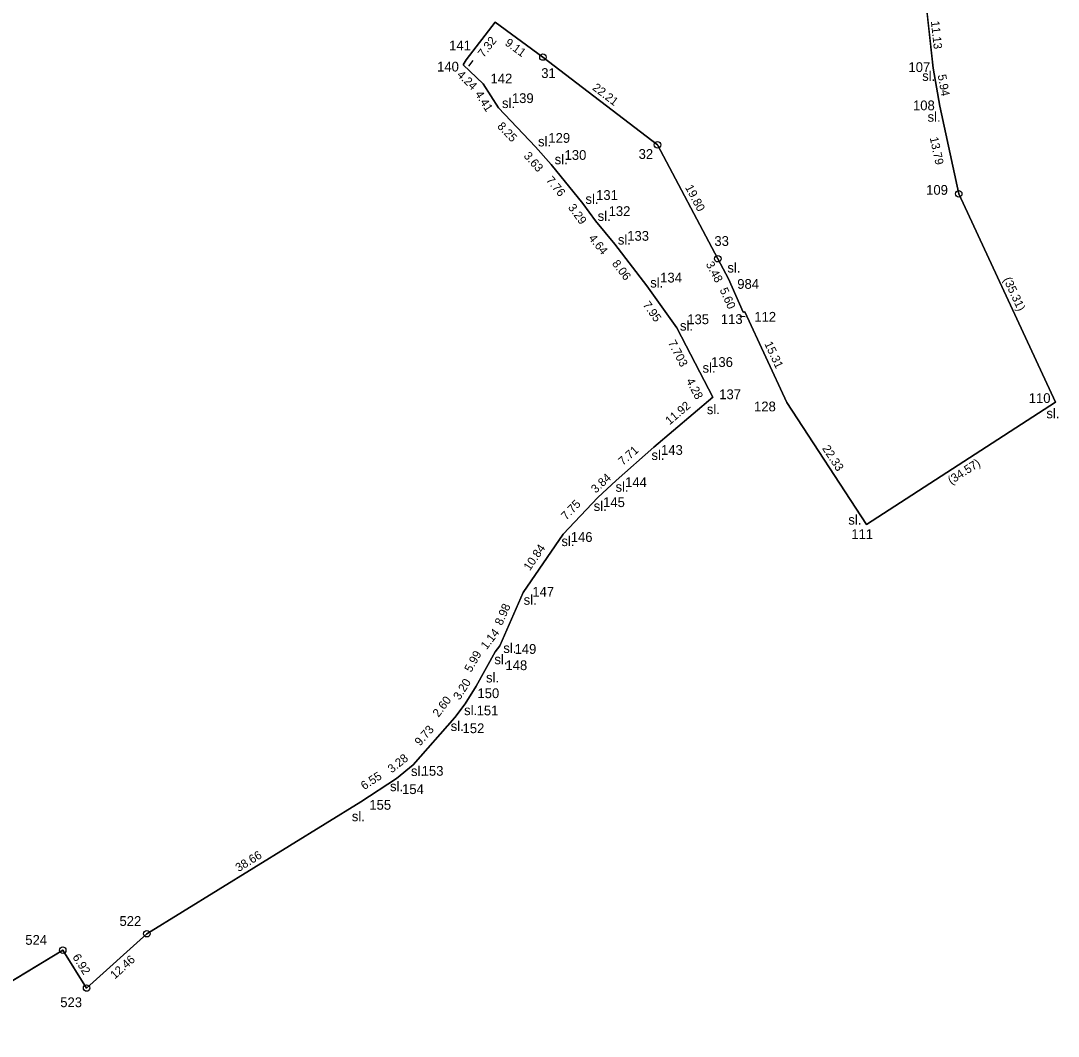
# Model space of a CAD drawing. Extents: x -555170 to -550532, y -1039598 to -1034701.
# Drawn here: x -553508.8 to -553349.4, y -1037298.8 to -1037142.8 of the extents above; entities that cross this region are included whole.
import ezdxf

# ---------------------------------------------------------------- set-up
doc = ezdxf.new("R2010")
doc.units = 0
for name, color, linetype in [('Vrstva 10', 7, 'Continuous'), ('Vrstva 40', 7, 'Continuous'), ('Vrstva 43', 7, 'Continuous'), ('Vrstva 48', 7, 'Continuous')]:
    doc.layers.add(name, color=color, linetype=linetype)

msp = doc.modelspace()

# ---------------------------------------------------------------- linework, layer by layer
at = {"layer": 'Vrstva 10'}
for p, q in [((-553439.38, -1037148.94), (-553440.05, -1037149.8)), ((-553397.55, -1037188.3), (-553398.36, -1037188.25))]:
    msp.add_line(p, q, dxfattribs=at)
at = {"layer": 'Vrstva 40'}
for p, q in [((-553368.67, -1037150.1), (-553369.86, -1037139.04)), ((-553440.38, -1037148.86), (-553435.92, -1037143.06)), ((-553435.92, -1037143.06), (-553428.6, -1037148.42)), ((-553440.84, -1037149.59), (-553440.38, -1037148.86)), ((-553437.77, -1037152.52), (-553440.84, -1037149.59)), ((-553428.6, -1037148.42), (-553410.99, -1037161.89)), ((-553367.62, -1037155.95), (-553368.67, -1037150.1)), ((-553435.44, -1037156.23), (-553437.77, -1037152.52)), ((-553429.76, -1037162.19), (-553435.44, -1037156.23)), ((-553364.73, -1037169.41), (-553367.62, -1037155.95)), ((-553427.36, -1037164.9), (-553429.76, -1037162.19)), ((-553410.99, -1037161.89), (-553401.73, -1037179.39)), ((-553422.45, -1037170.91), (-553427.36, -1037164.9)), ((-553349.86, -1037201.44), (-553364.73, -1037169.41)), ((-553420.52, -1037173.56), (-553422.45, -1037170.91)), ((-553417.58, -1037177.15), (-553420.52, -1037173.56)), ((-553412.65, -1037183.53), (-553417.58, -1037177.15)), ((-553401.73, -1037179.39), (-553400.1, -1037182.46)), ((-553400.1, -1037182.46), (-553397.85, -1037187.58)), ((-553408.03, -1037190.02), (-553412.65, -1037183.53)), ((-553397.85, -1037187.58), (-553397.59, -1037187.57)), ((-553397.59, -1037187.57), (-553391.13, -1037201.49)), ((-553404.48, -1037196.83), (-553408.03, -1037190.02)), ((-553402.51, -1037200.63), (-553404.48, -1037196.83)), ((-553411.55, -1037208.33), (-553402.51, -1037200.63)), ((-553391.13, -1037201.49), (-553378.91, -1037220.18)), ((-553378.91, -1037220.18), (-553349.86, -1037201.44)), ((-553417.35, -1037213.46), (-553411.55, -1037208.33)), ((-553420.17, -1037216.07), (-553417.35, -1037213.46)), ((-553425.49, -1037221.7), (-553420.17, -1037216.07)), ((-553431.62, -1037230.63), (-553425.49, -1037221.7)), ((-553435.21, -1037238.86), (-553431.62, -1037230.63)), ((-553435.92, -1037239.78), (-553435.21, -1037238.86)), ((-553438.85, -1037245.01), (-553435.92, -1037239.78)), ((-553440.56, -1037247.73), (-553438.85, -1037245.01)), ((-553442.13, -1037249.82), (-553440.56, -1037247.73)), ((-553448.52, -1037257.14), (-553442.13, -1037249.82)), ((-553451.08, -1037259.19), (-553448.52, -1037257.14)), ((-553456.55, -1037262.79), (-553451.08, -1037259.19)), ((-553489.45, -1037283.05), (-553456.55, -1037262.79)), ((-553498.7, -1037291.39), (-553489.45, -1037283.05)), ((-553524.22, -1037298.8), (-553502.37, -1037285.57)), ((-553502.37, -1037285.57), (-553498.7, -1037291.39))]:
    msp.add_line(p, q, dxfattribs=at)
at = {"layer": 'Vrstva 43'}
for p, q in [((-553435.92, -1037143.06), (-553435.92, -1037143.06)), ((-553440.84, -1037149.59), (-553440.84, -1037149.59)), ((-553440.38, -1037148.86), (-553440.38, -1037148.86)), ((-553428.6, -1037148.42), (-553428.6, -1037148.42)), ((-553368.67, -1037150.1), (-553368.67, -1037150.1)), ((-553437.77, -1037152.52), (-553437.77, -1037152.52)), ((-553435.44, -1037156.23), (-553435.44, -1037156.23)), ((-553367.62, -1037155.95), (-553367.62, -1037155.95)), ((-553429.76, -1037162.19), (-553429.76, -1037162.19)), ((-553410.99, -1037161.89), (-553410.99, -1037161.89)), ((-553427.36, -1037164.9), (-553427.36, -1037164.9)), ((-553364.73, -1037169.41), (-553364.73, -1037169.41)), ((-553422.45, -1037170.91), (-553422.45, -1037170.91)), ((-553420.52, -1037173.56), (-553420.52, -1037173.56)), ((-553417.58, -1037177.15), (-553417.58, -1037177.15)), ((-553401.73, -1037179.39), (-553401.73, -1037179.39)), ((-553400.1, -1037182.46), (-553400.1, -1037182.46)), ((-553412.65, -1037183.53), (-553412.65, -1037183.53)), ((-553397.85, -1037187.58), (-553397.85, -1037187.58)), ((-553397.59, -1037187.57), (-553397.59, -1037187.57)), ((-553408.03, -1037190.02), (-553408.03, -1037190.02)), ((-553404.48, -1037196.83), (-553404.48, -1037196.83)), ((-553402.51, -1037200.63), (-553402.51, -1037200.63)), ((-553391.13, -1037201.49), (-553391.13, -1037201.49)), ((-553349.86, -1037201.44), (-553349.86, -1037201.44)), ((-553411.55, -1037208.33), (-553411.55, -1037208.33)), ((-553417.35, -1037213.46), (-553417.35, -1037213.46)), ((-553420.17, -1037216.07), (-553420.17, -1037216.07)), ((-553378.91, -1037220.18), (-553378.91, -1037220.18)), ((-553425.49, -1037221.7), (-553425.49, -1037221.7)), ((-553431.62, -1037230.63), (-553431.62, -1037230.63)), ((-553435.21, -1037238.86), (-553435.21, -1037238.86)), ((-553435.92, -1037239.78), (-553435.92, -1037239.78)), ((-553438.85, -1037245.01), (-553438.85, -1037245.01)), ((-553440.56, -1037247.73), (-553440.56, -1037247.73)), ((-553442.13, -1037249.82), (-553442.13, -1037249.82)), ((-553448.52, -1037257.14), (-553448.52, -1037257.14)), ((-553451.08, -1037259.19), (-553451.08, -1037259.19)), ((-553456.55, -1037262.79), (-553456.55, -1037262.79)), ((-553489.45, -1037283.05), (-553489.45, -1037283.05)), ((-553502.37, -1037285.57), (-553502.37, -1037285.57)), ((-553498.7, -1037291.39), (-553498.7, -1037291.39))]:
    msp.add_line(p, q, dxfattribs=at)
for centre, radius in [((-553428.6, -1037148.42), 0.5), ((-553428.6, -1037148.42), 0.01), ((-553410.99, -1037161.89), 0.5), ((-553410.99, -1037161.89), 0.01), ((-553364.73, -1037169.41), 0.5), ((-553364.73, -1037169.41), 0.01), ((-553401.73, -1037179.39), 0.5), ((-553401.73, -1037179.39), 0.01), ((-553489.45, -1037283.05), 0.5), ((-553489.45, -1037283.05), 0.01), ((-553502.37, -1037285.57), 0.5), ((-553502.37, -1037285.57), 0.01), ((-553498.7, -1037291.39), 0.5), ((-553498.7, -1037291.39), 0.01)]:
    msp.add_circle(centre, radius, dxfattribs=at)
at = {"layer": 'Vrstva 48'}
msp.add_lwpolyline([(-553369.86, -1037139.04), (-553368.67, -1037150.1), (-553367.62, -1037155.95), (-553364.73, -1037169.41), (-553349.86, -1037201.44), (-553378.91, -1037220.18), (-553391.13, -1037201.49), (-553397.59, -1037187.57), (-553397.85, -1037187.58), (-553400.1, -1037182.46), (-553401.73, -1037179.39), (-553410.99, -1037161.89), (-553428.6, -1037148.42), (-553435.92, -1037143.06), (-553440.38, -1037148.86), (-553440.84, -1037149.59), (-553437.77, -1037152.52), (-553435.44, -1037156.23), (-553429.76, -1037162.19), (-553427.36, -1037164.9), (-553422.45, -1037170.91), (-553420.52, -1037173.56), (-553417.58, -1037177.15), (-553412.65, -1037183.53), (-553408.03, -1037190.02), (-553404.48, -1037196.83), (-553402.51, -1037200.63), (-553411.55, -1037208.33), (-553417.35, -1037213.46), (-553420.17, -1037216.07), (-553425.49, -1037221.7), (-553431.62, -1037230.63), (-553435.21, -1037238.86), (-553435.92, -1037239.78), (-553438.85, -1037245.01), (-553440.56, -1037247.73), (-553442.13, -1037249.82), (-553448.52, -1037257.14), (-553451.08, -1037259.19), (-553456.55, -1037262.79), (-553489.45, -1037283.05), (-553498.7, -1037291.39), (-553502.37, -1037285.57), (-553524.22, -1037298.8)], dxfattribs=at)

# ---------------------------------------------------------------- texts
at = {"layer": 'Vrstva 10'}
for s, rotation, p in [('11.13', 276.1411, (-553369, -1037142.93)), ('7.32', 52.441, (-553437.7, -1037148.58)), ('9.11', 323.7937, (-553434.55, -1037146.48)), ('4.24', 316.3367, (-553441.91, -1037151.27)), ('5.94', 280.1755, (-553367.96, -1037151.19)), ('22.21', 322.5709, (-553421.1, -1037153.34)), ('4.41', 302.1302, (-553439.09, -1037154.09)), ('8.25', 313.622, (-553435.71, -1037159.14)), ('13.79', 282.118, (-553369.18, -1037160.82)), ('3.63', 311.5284, (-553431.64, -1037163.66)), ('7.76', 309.2478, (-553428.18, -1037167.36)), ('19.80', 297.9091, (-553406.8, -1037168.43)), ('3.29', 306.0659, (-553424.81, -1037171.53)), ('4.64', 309.3155, (-553421.67, -1037176.28)), ('8.06', 307.6942, (-553418.06, -1037180.17)), ('3.48', 297.9091, (-553403.62, -1037180.22)), ('(35.31)', 294.9032, (-553357.91, -1037182.56)), ('5.60', 293.7232, (-553401.48, -1037184.16)), ('7.95', 305.4457, (-553413.32, -1037186.48)), ('7.703', 297.5327, (-553409.43, -1037192.28)), ('15.31', 294.8951, (-553394.61, -1037192.44)), ('4.28', 297.4032, (-553406.64, -1037198.13)), ('11.92', 40.4234, (-553409.13, -1037204.98)), ('7.71', 41.4922, (-553416.32, -1037211.21)), ('22.33', 303.1777, (-553385.76, -1037208.52)), ('(34.57)', 32.8258, (-553365.89, -1037214.1)), ('3.84', 42.7852, (-553420.49, -1037215.48)), ('7.75', 46.6216, (-553425.01, -1037219.61)), ('10.84', 55.5323, (-553430.62, -1037227.4)), ('8.98', 66.4327, (-553434.89, -1037235.81)), ('1.14', 52.3412, (-553437.26, -1037239.52)), ('5.99', 60.7412, (-553439.63, -1037243.01)), ('3.20', 57.8434, (-553441.39, -1037247.27)), ('2.60', 53.0863, (-553444.63, -1037249.89)), ('9.73', 48.8806, (-553447.47, -1037254.3)), ('3.28', 38.6871, (-553451.81, -1037258.44)), ('6.55', 33.3503, (-553456.05, -1037261.02)), ('38.66', 31.6206, (-553475.35, -1037273.6)), ('6.92', 302.2056, (-553500.93, -1037286.63)), ('12.46', 42.0263, (-553494.37, -1037290.1))]:
    msp.add_text(s, height=1.3, rotation=rotation, dxfattribs=at).set_placement(p)
at = {"layer": 'Vrstva 43'}
for s, p in [('141', (-553443.01, -1037147.39)), ('140', (-553444.86, -1037150.64)), ('107', (-553372.45, -1037150.71)), ('142', (-553436.65, -1037152.47)), ('31', (-553428.86, -1037151.63)), ('sl.', (-553370.34, -1037152.07)), ('sl.', (-553434.89, -1037156.25)), ('139', (-553433.37, -1037155.48)), ('108', (-553371.75, -1037156.59)), ('sl.', (-553369.51, -1037158.35)), ('sl.', (-553429.35, -1037162.14)), ('129', (-553427.77, -1037161.59)), ('130', (-553425.28, -1037164.21)), ('32', (-553413.9, -1037164.06)), ('sl.', (-553426.8, -1037164.89)), ('131', (-553420.43, -1037170.36)), ('109', (-553369.73, -1037169.57)), ('sl.', (-553422.07, -1037170.96)), ('sl.', (-553420.19, -1037173.58)), ('132', (-553418.51, -1037172.83)), ('133', (-553415.65, -1037176.63)), ('sl.', (-553417.09, -1037177.22)), ('33', (-553402.26, -1037177.42)), ('sl.', (-553400.26, -1037181.51)), ('134', (-553410.59, -1037183.04)), ('sl.', (-553412.12, -1037183.81)), ('984', (-553398.75, -1037184.01)), ('135', (-553406.43, -1037189.44)), ('113', (-553401.27, -1037189.41)), ('112', (-553396.13, -1037189.06)), ('sl.', (-553407.55, -1037190.43)), ('136', (-553402.76, -1037196.01)), ('sl.', (-553404.08, -1037196.89)), ('137', (-553401.52, -1037200.96)), ('110', (-553353.97, -1037201.54)), ('sl.', (-553403.42, -1037203.26)), ('128', (-553396.17, -1037202.83)), ('sl.', (-553351.26, -1037203.9)), ('sl.', (-553411.93, -1037210.3)), ('143', (-553410.46, -1037209.51)), ('sl.', (-553417.45, -1037215.18)), ('144', (-553415.98, -1037214.46)), ('sl.', (-553420.8, -1037218.13)), ('145', (-553419.36, -1037217.53)), ('sl.', (-553381.68, -1037220.23)), ('146', (-553424.33, -1037222.88)), ('111', (-553381.23, -1037222.43)), ('sl.', (-553425.76, -1037223.52)), ('sl.', (-553431.56, -1037232.53)), ('147', (-553430.23, -1037231.29)), ('sl.', (-553434.69, -1037239.94)), ('149', (-553432.96, -1037240.07)), ('sl.', (-553436.06, -1037241.67)), ('148', (-553434.36, -1037242.57)), ('sl.', (-553437.34, -1037244.46)), ('150', (-553438.66, -1037246.87)), ('sl.', (-553440.71, -1037249.48)), ('151', (-553438.79, -1037249.52)), ('sl.', (-553442.77, -1037251.92)), ('152', (-553440.95, -1037252.25)), ('sl.', (-553448.87, -1037258.83)), ('153', (-553447.23, -1037258.79)), ('sl.', (-553452.09, -1037261.16)), ('154', (-553450.24, -1037261.6)), ('155', (-553455.27, -1037264.01)), ('sl.', (-553457.96, -1037265.78)), ('522', (-553493.65, -1037281.85)), ('524', (-553508.12, -1037284.75)), ('523', (-553502.75, -1037294.33))]:
    msp.add_text(s, height=1.5, dxfattribs=at).set_placement(p)

doc.saveas('drawing.dxf')
